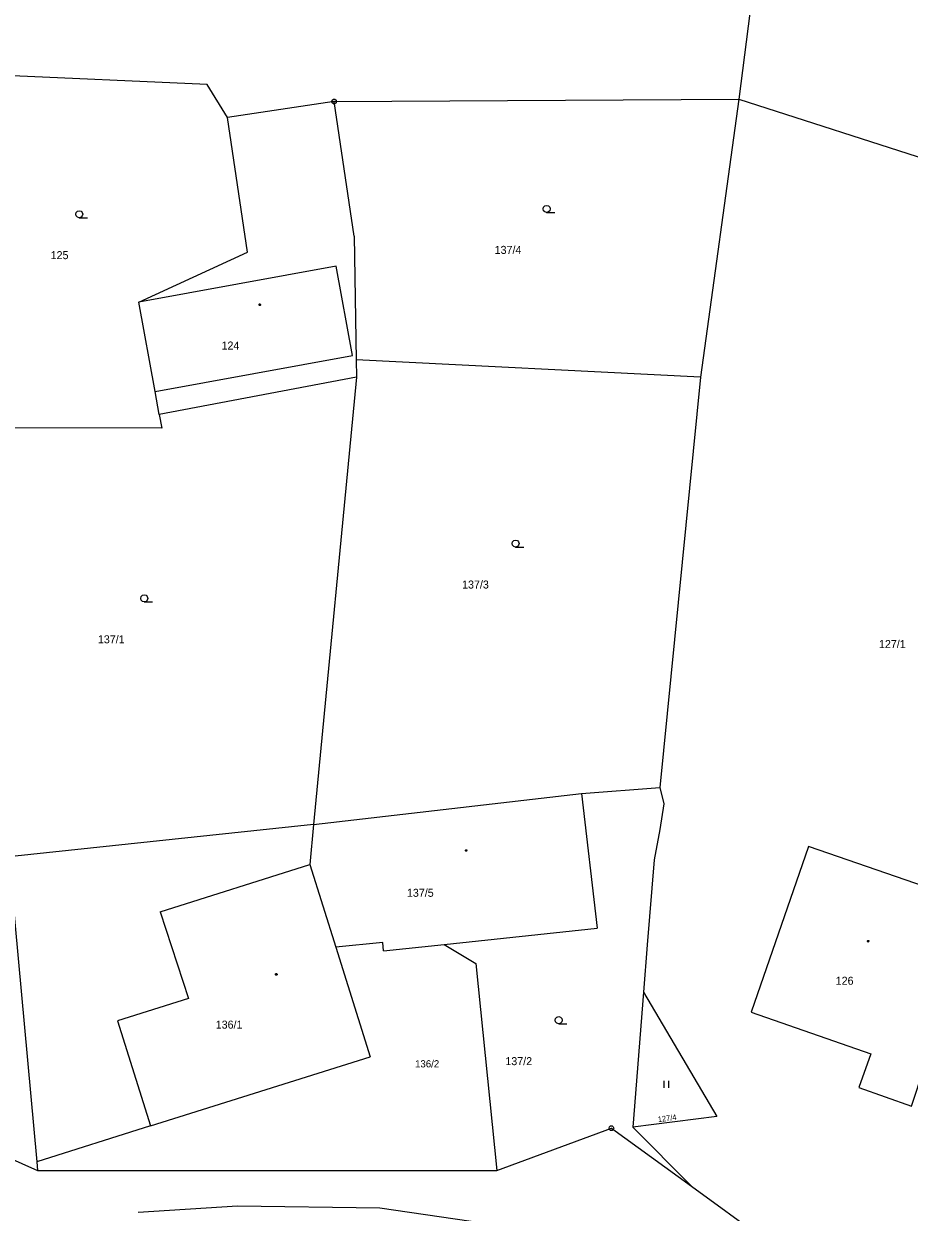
# Model space of a CAD drawing. Extents: x -871430 to -870620, y -1010094 to -1009649.
# Drawn here: x -870754.3 to -870707.3, y -1009884.4 to -1009821.3 of the extents above; entities that cross this region are included whole.
import ezdxf

# ---------------------------------------------------------------- set-up
doc = ezdxf.new("R2010")
doc.units = 0
for name, color, linetype in [('Vrstva 1', 7, 'Continuous'), ('Vrstva 2', 7, 'Continuous'), ('Vrstva 3', 7, 'Continuous'), ('Vrstva 4', 7, 'Continuous'), ('Vrstva 5', 7, 'Continuous'), ('Vrstva 8', 7, 'Continuous')]:
    doc.layers.add(name, color=color, linetype=linetype)

msp = doc.modelspace()

# ---------------------------------------------------------------- linework, layer by layer
at = {"layer": 'Vrstva 1'}
for p, q in [((-870711.73, -1009789.78), (-870716.33, -1009825.29)), ((-870744.58, -1009824.51), (-870763.36, -1009823.67)), ((-870743.5, -1009826.27), (-870744.58, -1009824.51)), ((-870737.83, -1009825.42), (-870743.5, -1009826.27)), ((-870737.83, -1009825.42), (-870716.33, -1009825.29)), ((-870736.76, -1009832.57), (-870737.83, -1009825.42)), ((-870716.33, -1009825.29), (-870718.37, -1009840.06)), ((-870716.33, -1009825.29), (-870689.91, -1009833.79)), ((-870742.43, -1009833.42), (-870743.5, -1009826.27)), ((-870736.76, -1009832.57), (-870736.66, -1009839.14)), ((-870748.21, -1009836.07), (-870742.43, -1009833.42)), ((-870747.34, -1009840.82), (-870748.21, -1009836.07)), ((-870718.37, -1009840.06), (-870736.66, -1009839.14)), ((-870736.66, -1009839.14), (-870736.64, -1009840.05)), ((-870736.64, -1009840.05), (-870747.12, -1009842.04)), ((-870736.64, -1009840.05), (-870738.92, -1009863.81)), ((-870718.37, -1009840.06), (-870720.52, -1009861.85)), ((-870747.12, -1009842.04), (-870747.34, -1009840.82)), ((-870747.12, -1009842.04), (-870746.99, -1009842.77)), ((-870746.99, -1009842.77), (-870756.72, -1009842.74)), ((-870738.92, -1009863.81), (-870724.68, -1009862.16)), ((-870724.68, -1009862.16), (-870720.52, -1009861.85)), ((-870724.68, -1009862.16), (-870723.85, -1009869.32)), ((-870720.52, -1009861.85), (-870720.32, -1009862.72)), ((-870720.32, -1009862.72), (-870720.53, -1009864.07)), ((-870738.92, -1009863.81), (-870755.12, -1009865.52)), ((-870738.92, -1009863.81), (-870739.12, -1009865.94)), ((-870720.53, -1009864.07), (-870720.83, -1009865.68)), ((-870755.12, -1009865.52), (-870753.63, -1009881.72)), ((-870739.12, -1009865.94), (-870737.74, -1009870.33)), ((-870720.83, -1009865.68), (-870721.19, -1009870.2)), ((-870731.99, -1009870.18), (-870723.85, -1009869.32)), ((-870735.25, -1009870.07), (-870737.74, -1009870.33)), ((-870737.74, -1009870.33), (-870735.91, -1009876.14)), ((-870735.2, -1009870.52), (-870735.25, -1009870.07)), ((-870735.2, -1009870.52), (-870731.99, -1009870.18)), ((-870731.99, -1009870.18), (-870730.3, -1009871.19)), ((-870721.19, -1009870.2), (-870721.39, -1009872.71)), ((-870730.3, -1009871.19), (-870729.18, -1009882.19)), ((-870721.39, -1009872.71), (-870721.96, -1009879.88)), ((-870721.39, -1009872.71), (-870717.5, -1009879.31)), ((-870747.58, -1009879.82), (-870735.91, -1009876.14)), ((-870747.58, -1009879.82), (-870753.63, -1009881.72)), ((-870717.5, -1009879.31), (-870721.96, -1009879.88)), ((-870721.96, -1009879.88), (-870718.85, -1009883.01)), ((-870729.18, -1009882.19), (-870723.1, -1009879.94)), ((-870723.1, -1009879.94), (-870718.85, -1009883.01)), ((-870755.26, -1009881.44), (-870753.59, -1009882.19)), ((-870753.63, -1009881.72), (-870753.59, -1009882.19)), ((-870753.59, -1009882.19), (-870729.18, -1009882.19)), ((-870718.85, -1009883.01), (-870713.34, -1009887))]:
    msp.add_line(p, q, dxfattribs=at)
for points in [[(-870704.01, -1009868.47), (-870703.85, -1009868.01), (-870712.63, -1009864.98), (-870715.68, -1009873.77), (-870709.31, -1009875.99), (-870709.95, -1009877.77), (-870707.16, -1009878.76), (-870706.5, -1009876.79)], [(-870727.39, -1009885.35), (-870735.4, -1009884.18), (-870742.97, -1009884.08), (-870748.24, -1009884.41)]]:
    msp.add_lwpolyline(points, dxfattribs=at)
at = {"layer": 'Vrstva 3'}
for p, q in [((-870720.305, -1009877.415), (-870720.305, -1009877.79)), ((-870720.055, -1009877.79), (-870720.055, -1009877.415))]:
    msp.add_line(p, q, dxfattribs=at)
for points in [[(-870751.37, -1009831.59), (-870751.465, -1009831.565), (-870751.532, -1009831.495), (-870751.558, -1009831.402), (-870751.532, -1009831.31), (-870751.465, -1009831.24), (-870751.37, -1009831.215), (-870751.275, -1009831.24), (-870751.208, -1009831.31), (-870751.182, -1009831.402), (-870751.208, -1009831.495), (-870751.275, -1009831.565), (-870751.37, -1009831.59), (-870750.932, -1009831.59)], [(-870726.54, -1009831.31), (-870726.635, -1009831.285), (-870726.702, -1009831.215), (-870726.728, -1009831.122), (-870726.702, -1009831.03), (-870726.635, -1009830.96), (-870726.54, -1009830.935), (-870726.445, -1009830.96), (-870726.378, -1009831.03), (-870726.352, -1009831.122), (-870726.378, -1009831.215), (-870726.445, -1009831.285), (-870726.54, -1009831.31), (-870726.102, -1009831.31)], [(-870728.19, -1009849.08), (-870728.285, -1009849.055), (-870728.352, -1009848.985), (-870728.378, -1009848.892), (-870728.352, -1009848.8), (-870728.285, -1009848.73), (-870728.19, -1009848.705), (-870728.095, -1009848.73), (-870728.028, -1009848.8), (-870728.002, -1009848.892), (-870728.028, -1009848.985), (-870728.095, -1009849.055), (-870728.19, -1009849.08), (-870727.752, -1009849.08)], [(-870747.92, -1009851.99), (-870748.015, -1009851.965), (-870748.082, -1009851.895), (-870748.108, -1009851.802), (-870748.082, -1009851.71), (-870748.015, -1009851.64), (-870747.92, -1009851.615), (-870747.825, -1009851.64), (-870747.758, -1009851.71), (-870747.732, -1009851.802), (-870747.758, -1009851.895), (-870747.825, -1009851.965), (-870747.92, -1009851.99), (-870747.482, -1009851.99)], [(-870725.9, -1009874.39), (-870725.995, -1009874.365), (-870726.062, -1009874.295), (-870726.088, -1009874.202), (-870726.062, -1009874.11), (-870725.995, -1009874.04), (-870725.9, -1009874.015), (-870725.805, -1009874.04), (-870725.738, -1009874.11), (-870725.712, -1009874.202), (-870725.738, -1009874.295), (-870725.805, -1009874.365), (-870725.9, -1009874.39), (-870725.462, -1009874.39)]]:
    msp.add_lwpolyline(points, dxfattribs=at)
at = {"layer": 'Vrstva 4'}
for p, q in [((-870737.72, -1009834.16), (-870748.21, -1009836.07)), ((-870736.85, -1009838.91), (-870737.72, -1009834.16)), ((-870747.34, -1009840.82), (-870736.85, -1009838.91)), ((-870747.08, -1009868.45), (-870739.12, -1009865.94)), ((-870747.08, -1009868.45), (-870745.57, -1009873.05)), ((-870745.57, -1009873.05), (-870749.34, -1009874.24)), ((-870749.34, -1009874.24), (-870747.58, -1009879.82))]:
    msp.add_line(p, q, dxfattribs=at)
at = {"layer": 'Vrstva 5'}
for points in [[(-870741.78, -1009836.168), (-870741.755, -1009836.172), (-870741.742, -1009836.195), (-870741.738, -1009836.21), (-870741.742, -1009836.232), (-870741.763, -1009836.25), (-870741.78, -1009836.252), (-870741.802, -1009836.245), (-870741.818, -1009836.23), (-870741.822, -1009836.21), (-870741.818, -1009836.188), (-870741.798, -1009836.17), (-870741.78, -1009836.168)], [(-870730.81, -1009865.148), (-870730.785, -1009865.152), (-870730.773, -1009865.175), (-870730.768, -1009865.19), (-870730.773, -1009865.212), (-870730.793, -1009865.23), (-870730.81, -1009865.232), (-870730.832, -1009865.225), (-870730.848, -1009865.21), (-870730.852, -1009865.19), (-870730.848, -1009865.168), (-870730.828, -1009865.15), (-870730.81, -1009865.148)], [(-870709.45, -1009869.968), (-870709.425, -1009869.972), (-870709.412, -1009869.995), (-870709.408, -1009870.01), (-870709.412, -1009870.032), (-870709.432, -1009870.05), (-870709.45, -1009870.052), (-870709.472, -1009870.045), (-870709.487, -1009870.03), (-870709.492, -1009870.01), (-870709.487, -1009869.988), (-870709.467, -1009869.97), (-870709.45, -1009869.968)], [(-870740.9, -1009871.728), (-870740.875, -1009871.732), (-870740.862, -1009871.755), (-870740.858, -1009871.77), (-870740.862, -1009871.792), (-870740.883, -1009871.81), (-870740.9, -1009871.812), (-870740.922, -1009871.805), (-870740.938, -1009871.79), (-870740.942, -1009871.77), (-870740.938, -1009871.748), (-870740.918, -1009871.73), (-870740.9, -1009871.728)]]:
    msp.add_lwpolyline(points, dxfattribs=at)
at = {"layer": 'Vrstva 8'}
for p, q in [((-870737.842, -1009825.42), (-870737.818, -1009825.42)), ((-870723.112, -1009879.94), (-870723.088, -1009879.94))]:
    msp.add_line(p, q, dxfattribs=at)
for points in [[(-870737.792, -1009825.3), (-870737.73, -1009825.348), (-870737.705, -1009825.42), (-870737.73, -1009825.492), (-870737.792, -1009825.54), (-870737.867, -1009825.54), (-870737.93, -1009825.492), (-870737.955, -1009825.42), (-870737.93, -1009825.348), (-870737.867, -1009825.3), (-870737.792, -1009825.3)], [(-870723.062, -1009879.82), (-870723, -1009879.867), (-870722.975, -1009879.94), (-870723, -1009880.012), (-870723.062, -1009880.06), (-870723.138, -1009880.06), (-870723.2, -1009880.012), (-870723.225, -1009879.94), (-870723.2, -1009879.867), (-870723.138, -1009879.82), (-870723.062, -1009879.82)]]:
    msp.add_lwpolyline(points, dxfattribs=at)

# ---------------------------------------------------------------- texts
at = {"layer": 'Vrstva 2'}
for s, height, p in [('137/4', 0.425, (-870729.302, -1009833.51)), ('125', 0.425, (-870752.892, -1009833.79)), ('124', 0.425, (-870743.812, -1009838.59)), ('137/3', 0.425, (-870731.032, -1009851.28)), ('137/1', 0.425, (-870750.382, -1009854.19)), ('127/1', 0.425, (-870708.882, -1009854.44)), ('137/5', 0.425, (-870733.962, -1009867.65)), ('126', 0.425, (-870711.182, -1009872.32)), ('136/1', 0.425, (-870744.122, -1009874.65)), ('136/2', 0.3825, (-870733.528, -1009876.71)), ('137/2', 0.425, (-870728.732, -1009876.59))]:
    msp.add_text(s, height=height, dxfattribs=at).set_placement(p)
msp.add_text('127/4', height=0.2975, rotation=7.39116, dxfattribs=at).set_placement((-870720.613, -1009879.621))

doc.saveas('drawing.dxf')
